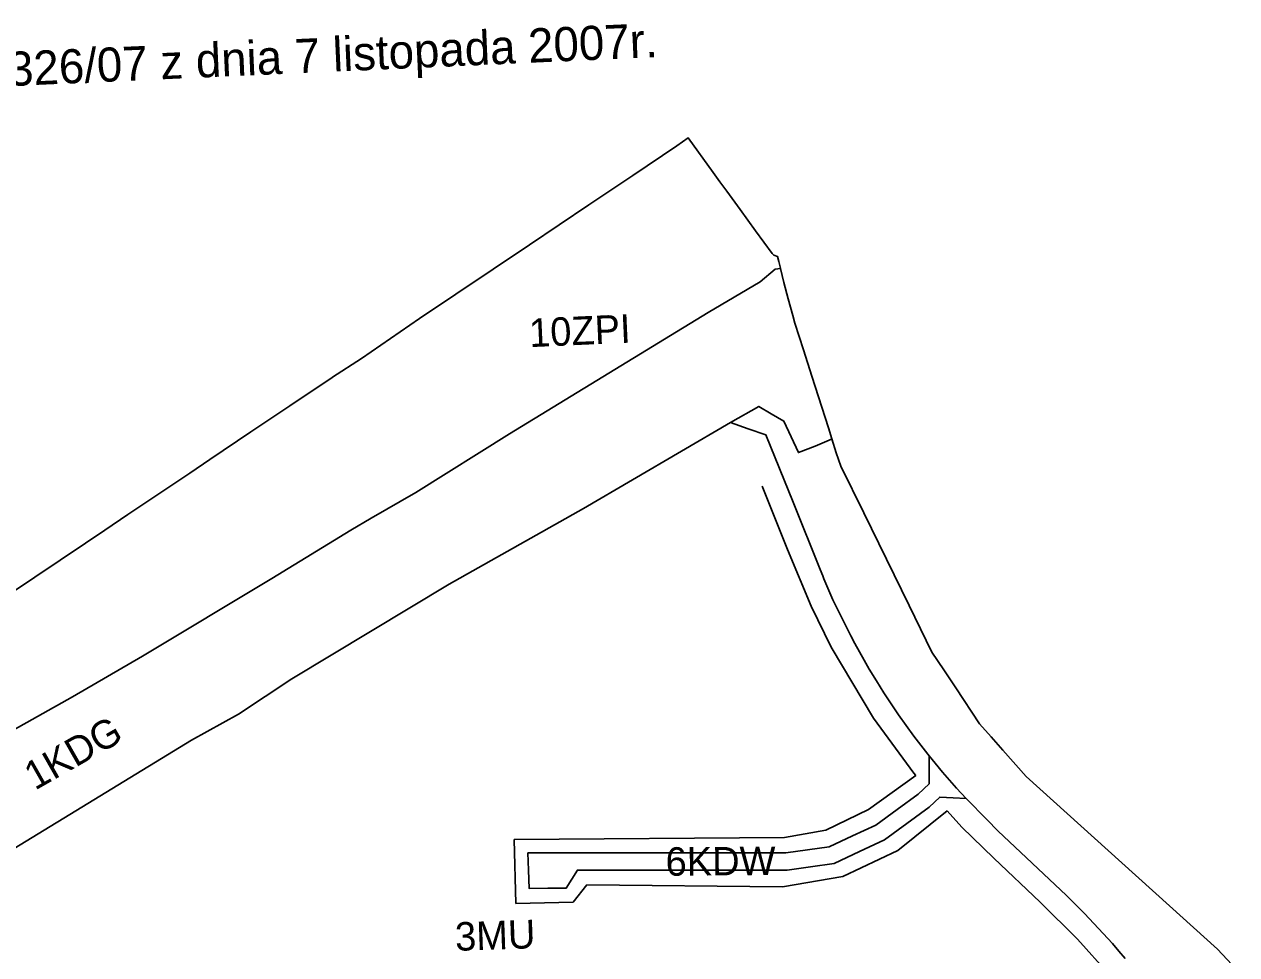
# Model space of a CAD drawing. Extents: x 7418021 to 7419743, y 5540231 to 5541685.
# Drawn here: x 7419247.1 to 7419673.1, y 5541345.6 to 5541672.4 of the extents above; entities that cross this region are included whole.
import ezdxf

# ---------------------------------------------------------------- set-up
doc = ezdxf.new("R2010")
doc.units = 0
for name, color, linetype in [('info', 7, 'Continuous'), ('linie_rozgraniczajace', 7, 'Continuous'), ('linie_zabudowy_nieprzekraczalne', 7, 'Continuous'), ('oznaczenia_przeznaczen', 7, 'Continuous')]:
    doc.layers.add(name, color=color, linetype=linetype)

msp = doc.modelspace()

# ---------------------------------------------------------------- linework, layer by layer
at = {"layer": 'linie_rozgraniczajace'}
for points in [[(7419241.95, 5541472.21), (7419268.64, 5541490.14), (7419275.46, 5541494.71), (7419283.53, 5541500.13), (7419298.32, 5541510.07), (7419305.31, 5541514.76), (7419312.3, 5541519.46), (7419326.79, 5541529.18), (7419340.4, 5541538.33), (7419355.34, 5541548.36), (7419355.38, 5541548.38), (7419365.64, 5541555.03), (7419386.04, 5541568.98), (7419424.6, 5541594.87), (7419435.07, 5541601.9), (7419445.51, 5541608.91), (7419460.97, 5541619.3), (7419476.44, 5541629.68), (7419480.37, 5541632.51), (7419489.22, 5541620.28), (7419491.57, 5541617.03), (7419493.92, 5541613.79), (7419498.62, 5541607.3), (7419504.03, 5541599.82), (7419509.96, 5541591.82), (7419510.47, 5541591.3), (7419511.77, 5541590.84), (7419512.25, 5541589.01), (7419512.72, 5541587.18), (7419512.86, 5541586.59), (7419510.98, 5541586.38), (7419505.71, 5541581.92), (7419487.4, 5541571.14), (7419417.67, 5541528.52), (7419384.66, 5541507.89), (7419369, 5541498.86), (7419361.92, 5541494.7), (7419334.11, 5541477.66), (7419288.72, 5541450.47), (7419264.06, 5541436.17), (7419197.72, 5541398.92)], [(7419197.72, 5541398.92), (7419264.06, 5541436.17), (7419288.72, 5541450.47), (7419334.11, 5541477.66), (7419361.92, 5541494.7), (7419369, 5541498.86), (7419384.66, 5541507.89), (7419417.67, 5541528.52), (7419487.4, 5541571.14), (7419505.71, 5541581.92), (7419510.98, 5541586.38), (7419512.86, 5541586.59), (7419514, 5541581.7), (7419515.58, 5541575.9), (7419517.17, 5541570.09), (7419517.92, 5541567.38), (7419520.89, 5541558.05), (7419523.86, 5541548.73), (7419529.64, 5541530.61), (7419530.88, 5541526.72), (7419530.75, 5541526.66), (7419525.06, 5541524.15), (7419519.12, 5541521.94), (7419516.58, 5541527.46), (7419514.04, 5541532.97), (7419509.6, 5541535.56), (7419505.16, 5541538.14), (7419495.31, 5541532.45), (7419443.58, 5541502.24), (7419396.42, 5541475.75), (7419368.75, 5541459.1), (7419341.09, 5541442.45), (7419331.76, 5541436.27), (7419322.44, 5541430.08), (7419305.93, 5541420.97), (7419243.56, 5541382.86)], [(7419495.31, 5541532.45), (7419505.16, 5541538.14), (7419509.6, 5541535.56), (7419514.04, 5541532.97), (7419516.58, 5541527.46), (7419519.12, 5541521.94), (7419525.06, 5541524.15), (7419530.75, 5541526.66), (7419530.88, 5541526.72), (7419532.42, 5541521.88), (7419534.08, 5541517.11), (7419542.07, 5541500.8), (7419550.06, 5541484.48), (7419558.05, 5541468.17), (7419566.03, 5541451.86), (7419570.21, 5541445.57), (7419574.39, 5541439.27), (7419582.75, 5541426.68), (7419586.84, 5541422.05), (7419590.94, 5541417.42), (7419599.13, 5541408.16), (7419632.73, 5541377.86), (7419649.53, 5541362.71), (7419666.33, 5541347.56), (7419673.13, 5541340.23)], [(7419396.42, 5541475.75), (7419443.58, 5541502.24), (7419495.31, 5541532.45)], [(7419495.31, 5541532.45), (7419501.51, 5541530.32), (7419507.71, 5541528.18), (7419517.24, 5541504.5), (7419526.78, 5541480.82), (7419527.69, 5541478.59), (7419528.09, 5541477.62), (7419529.15, 5541475.16), (7419530.21, 5541472.7), (7419531.27, 5541470.24), (7419533.74, 5541465.05), (7419535.63, 5541461.3), (7419537.51, 5541457.56), (7419538.95, 5541454.86), (7419542.21, 5541449), (7419544.02, 5541445.83), (7419546.56, 5541441.71), (7419549.09, 5541437.59), (7419551.67, 5541433.73), (7419554.24, 5541429.87), (7419556.96, 5541426.09), (7419559.67, 5541422.32), (7419562.11, 5541419.16), (7419564.55, 5541416), (7419565.02, 5541415.42), (7419565.02, 5541410.52), (7419565.02, 5541405.62), (7419561.18, 5541401.95), (7419553.77, 5541396.53), (7419546.36, 5541391.11), (7419538.14, 5541387.29), (7419529.93, 5541383.47), (7419522.32, 5541382.38), (7419514.72, 5541381.3), (7419469.41, 5541381.3), (7419424.1, 5541381.3), (7419424.29, 5541375.3), (7419424.54, 5541368.81), (7419431.05, 5541368.89), (7419437.55, 5541368.96), (7419439.53, 5541372.13), (7419441.5, 5541375.3), (7419478.32, 5541375.3), (7419515.14, 5541375.3), (7419523.4, 5541376.48), (7419531.66, 5541377.65), (7419540.54, 5541381.78), (7419549.42, 5541385.91), (7419557.23, 5541391.62), (7419565.04, 5541397.34), (7419566.92, 5541399.14), (7419568.81, 5541400.94), (7419573.46, 5541400.66), (7419578.1, 5541400.38), (7419585.39, 5541392.9), (7419589.24, 5541389.1), (7419601.28, 5541377.7), (7419613.33, 5541366.31), (7419616.5, 5541363.19), (7419619.67, 5541360.08), (7419624.6, 5541354.77), (7419629.53, 5541349.47), (7419631.75, 5541346.86), (7419633.97, 5541344.26)], [(7419633.97, 5541344.26), (7419631.75, 5541346.86), (7419629.53, 5541349.47), (7419624.6, 5541354.77), (7419619.67, 5541360.08), (7419616.5, 5541363.19), (7419613.33, 5541366.31), (7419601.28, 5541377.7), (7419589.24, 5541389.1), (7419585.39, 5541392.9), (7419578.1, 5541400.38), (7419574.67, 5541404.05), (7419572.22, 5541406.84), (7419569.78, 5541409.64), (7419567.16, 5541412.82), (7419565.02, 5541415.42), (7419564.55, 5541416), (7419562.11, 5541419.16), (7419559.67, 5541422.32), (7419556.96, 5541426.09), (7419554.24, 5541429.87), (7419551.67, 5541433.73), (7419549.09, 5541437.59), (7419546.56, 5541441.71), (7419544.02, 5541445.83), (7419542.21, 5541449), (7419538.95, 5541454.86), (7419537.51, 5541457.56), (7419535.63, 5541461.3), (7419533.74, 5541465.05), (7419531.27, 5541470.24), (7419530.21, 5541472.7), (7419529.15, 5541475.16), (7419528.09, 5541477.62), (7419527.69, 5541478.59), (7419526.78, 5541480.82), (7419517.24, 5541504.5), (7419507.71, 5541528.18), (7419501.51, 5541530.32), (7419495.31, 5541532.45)], [(7419243.56, 5541382.86), (7419305.93, 5541420.97), (7419322.44, 5541430.08), (7419331.76, 5541436.27), (7419341.09, 5541442.45), (7419368.75, 5541459.1), (7419396.42, 5541475.75)]]:
    msp.add_lwpolyline(points, dxfattribs=at)
msp.add_lwpolyline([(7419565.02, 5541415.42), (7419567.16, 5541412.82), (7419569.78, 5541409.64), (7419572.22, 5541406.84), (7419574.67, 5541404.05), (7419578.1, 5541400.38), (7419573.46, 5541400.66), (7419568.81, 5541400.94), (7419566.92, 5541399.14), (7419565.04, 5541397.34), (7419557.23, 5541391.62), (7419549.42, 5541385.91), (7419540.54, 5541381.78), (7419531.66, 5541377.65), (7419523.4, 5541376.48), (7419515.14, 5541375.3), (7419478.32, 5541375.3), (7419441.5, 5541375.3), (7419439.53, 5541372.13), (7419437.55, 5541368.96), (7419431.05, 5541368.89), (7419424.54, 5541368.81), (7419424.29, 5541375.3), (7419424.1, 5541381.3), (7419469.41, 5541381.3), (7419514.72, 5541381.3), (7419522.32, 5541382.38), (7419529.93, 5541383.47), (7419538.14, 5541387.29), (7419546.36, 5541391.11), (7419553.77, 5541396.53), (7419561.18, 5541401.95), (7419565.02, 5541405.62), (7419565.02, 5541410.52)], close=True, dxfattribs=at)
at = {"layer": 'linie_zabudowy_nieprzekraczalne'}
for points in [[(7419515.32, 5541487.86), (7419506.35, 5541510.15)], [(7419523.6, 5541467.95), (7419515.32, 5541487.86)], [(7419530.59, 5541453.53), (7419523.6, 5541467.95)], [(7419545.47, 5541428.61), (7419530.59, 5541453.53)], [(7419559.7, 5541409.3), (7419545.47, 5541428.61)], [(7419543.69, 5541396.59), (7419560.42, 5541408.5)], [(7419560.42, 5541408.5), (7419559.7, 5541409.3)], [(7419528.73, 5541389.29), (7419543.69, 5541396.59)], [(7419571.42, 5541396.15), (7419554.09, 5541382.22)], [(7419576.58, 5541390.36), (7419571.42, 5541396.15)], [(7419514.19, 5541386.68), (7419528.73, 5541389.29)], [(7419587.74, 5541379.51), (7419576.58, 5541390.36)], [(7419419.25, 5541386.07), (7419514.19, 5541386.68)], [(7419419.81, 5541363.53), (7419419.25, 5541386.07)], [(7419554.09, 5541382.22), (7419534.69, 5541373)], [(7419604.06, 5541364.07), (7419587.74, 5541379.51)], [(7419534.69, 5541373), (7419513.52, 5541369.4)], [(7419444.78, 5541370.15), (7419440.04, 5541364.04)], [(7419513.52, 5541369.4), (7419444.78, 5541370.15)], [(7419440.04, 5541364.04), (7419419.81, 5541363.53)], [(7419617.19, 5541351.01), (7419604.06, 5541364.07)], [(7419628.25, 5541338.65), (7419617.19, 5541351.01)]]:
    msp.add_lwpolyline(points, dxfattribs=at)

# ---------------------------------------------------------------- texts
at = {"layer": 'info'}
msp.add_text('opracowane w skali 1:2000 pochodzące z Miejscowego Planu Zagospodarowania Przestrzennego "Skotnicka-Działowskiego" zatwierdzonego uchwałą RMK Nr XXVI/326/07 z dnia 7 listopada 2007r.', height=12, rotation=2.5711, dxfattribs=at).set_placement((7418064.81, 5541597.78))
at = {"layer": 'oznaczenia_przeznaczen'}
for s, rotation, p in [('10ZPI', 2.5711, (7419424.72, 5541558.96)), ('1KDG', 29.6189, (7419250.89, 5541403.15)), ('6KDW', 0.3694, (7419472.48, 5541373.29)), ('3MU', 1.9767, (7419398.65, 5541346.91))]:
    msp.add_text(s, height=10, rotation=rotation, dxfattribs=at).set_placement(p)

doc.saveas('drawing.dxf')
